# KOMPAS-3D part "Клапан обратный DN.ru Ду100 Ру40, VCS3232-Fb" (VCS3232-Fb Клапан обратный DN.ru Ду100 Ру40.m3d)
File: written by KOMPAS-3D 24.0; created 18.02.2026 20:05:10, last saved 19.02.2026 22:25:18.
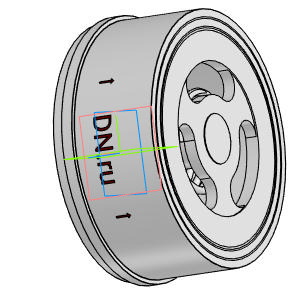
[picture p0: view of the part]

Document properties: Автор: R2D2; Полное имя файла: D:\Работа\Клапаны обратные\VCS3232-Fb Клапан обратный DN.ru Ду15-100\DN100\VCS3232-Fb Клапан обратный DN.ru Ду100 Ру40.m3d

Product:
- Body: Тело 1  | qty 1
    Масса: 2.494534
- Body: Тело 2  | qty 1
    Масса: 1.619958
- Part/product: Клапан обратный DN.ru Ду100 Ру40  | designation VCS3232-Fb
    Масса: 2.84
    Раздел спецификации: Прочие изделия
    Примечание: D100-03713
    additional columns: 1; D100-03713

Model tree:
1. Операция без истории:1
2. Операция без истории:2

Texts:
  Точка начала. Х
  Точка начала. Y
  Точка начала. Z
  VCS3232-Fb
